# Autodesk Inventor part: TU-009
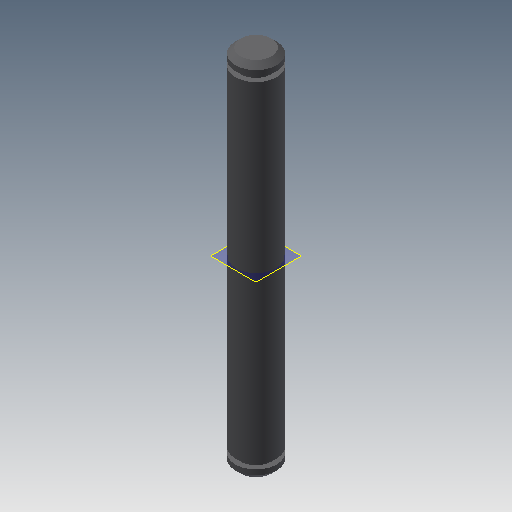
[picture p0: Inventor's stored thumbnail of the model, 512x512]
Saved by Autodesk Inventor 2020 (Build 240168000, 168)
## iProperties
Created: 2002-07
Part Number: TU-009
Document SubType Name: Modeling
Designer: PN
Description: Long Pin
Density: 8.08 g/cm^3
Mass: 27.8886 g
Surface Area: 19.0317 cm^2
Volume: 3.45156 cm^3
Material: Stainless Steel
Appearance: 128,128,128
Control State: 0
Master: False
Checked Out: False
Shininess: 64.0
Angle Display Precision: 2
Document Length Units: 11269
Document Angle Units: 11279
Document Time Units: 11290
Document Mass Units: 11286
Document Length Units Precision: 3
Document Angle Units Precision: 2
Compacted: True
LENGTH: 1.000 in
Density: 0.0
Volumn: 0.0
Area: 0.0
PropertySet Name: Model Information
Author: PN
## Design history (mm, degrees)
sketch "Sketch1"
  geometry: L1 (4, 67)-(4, 3); L2 (3, 67)-(4, 67); L3 (3, 68)-(3, 67); L4 (4, 68)-(3, 68); L5 (4, 69)-(4, 68); L6 (0, 70)-(3, 70); L7 (3, 70)-(4, 69); L8 (4, 3)-(3, 3); L9 (3, 3)-(3, 2); L10 (3, 2)-(4, 2); L11 (4, 2)-(4, 1); L12 (4, 1)-(3, 0); L13 (0, 70)-(0, 0); L14 (0, 0)-(3, 0); 1 further point
  constraints: 28 end point, 5 perpendicular, 3 collinear, 2 equal length, 1 coincident, 1 horizontal, 1 parallel
  dimensions: "d4" = 65 distance between parallel lines of L4 L8; "d5" = 1 distance between parallel lines of L4 L2; "d6" = 66 distance between parallel lines of L4 L10; "d7" = 2 distance between parallel lines of L4 L6; "d19" = 8 diameter of L11 L13; "d20" = 45 deg angle of L14 L12; "d23" = 1 distance from line of L12.end L11; "d24" = 1 distance between parallel lines of L3 L1
revolve "Revolution1" sketch "Sketch1" stored, may be unused: angle "d18" = 90 deg
workplane "Work Plane1"
body "Solid1"
other parameters: "LENGTH" = 25.4 [user parameter]
